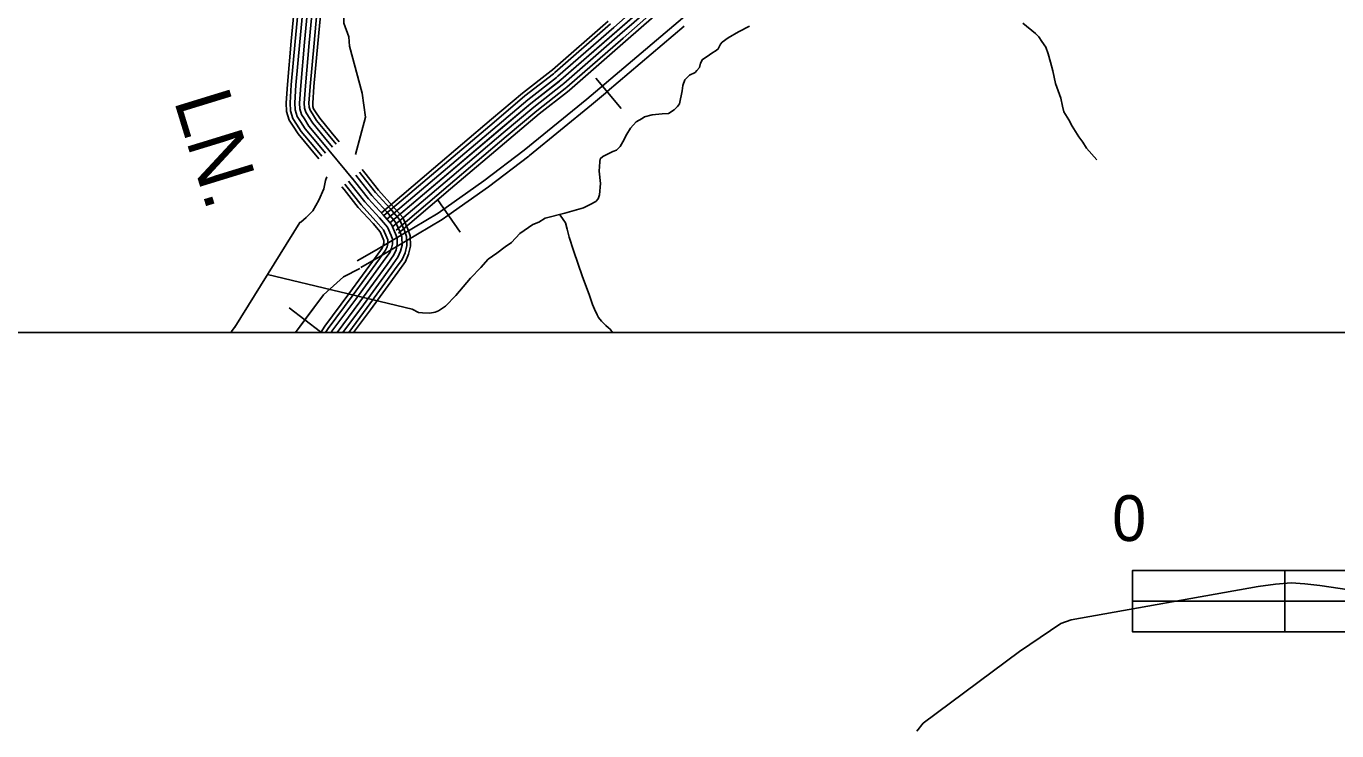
# Model space of a CAD drawing. Extents: x 1577619 to 1828281, y 483481 to 598136.
# Drawn here: x 1672781 to 1681374, y 505510 to 510126 of the extents above; entities that cross this region are included whole.
import ezdxf

# ---------------------------------------------------------------- set-up
doc = ezdxf.new("R2010")
doc.units = 0
for name, color, linetype in [('DESIGN - CONTOURS - Intermediate with optional Text', 7, 'Continuous'), ('DESIGN - ROW - Right-of-Way and Easement Labels', 7, 'Continuous'), ('DESIGN - SHEET - Corner Text', 7, 'Continuous'), ('DESIGN - SHEET - Linework', 7, 'Continuous'), ('DESIGN - TRANSPORTATION - Text', 7, 'Continuous'), ('SURVEY - CONTROL with Text', 7, 'Continuous'), ('SURVEY - TRANSPORTATION - Roads', 7, 'Continuous')]:
    doc.layers.add(name, color=color, linetype=linetype)

msp = doc.modelspace()

# ---------------------------------------------------------------- linework, layer by layer
at = {"layer": 'DESIGN - CONTOURS - Intermediate with optional Text'}
for p, q in [((1676682.7, 509587.5), (1676514.7, 509786)), ((1675627.1, 508777.1), (1675478.1, 508990.2)), ((1674504, 508280), (1674711.5, 508123.4))]:
    msp.add_line(p, q, dxfattribs=at)
for points in [[(1674951, 508587.6), (1675078.1, 508661.1), (1675481.1, 508901.7), (1675782.4, 509112.4), (1676046.1, 509313.4), (1676456.1, 509648.1), (1677512.9, 510542.5), (1678108.9, 511056.8), (1678611.5, 511476.1), (1678813.4, 511646.9), (1678948.4, 511774.5), (1679168.8, 511983.5), (1679370.4, 512186.2), (1679519.7, 512344), (1679684, 512530.1), (1679821.1, 512703.3), (1679957.3, 512912.7), (1680046.6, 513052.1), (1680161.2, 513242.5), (1680189.5, 513292.2)], [(1676590.3, 509699), (1677094, 510125.4)], [(1676080.9, 509278), (1676487.7, 509610.1), (1676591.3, 509697.8)], [(1675545, 508886.7), (1675811.3, 509072.8), (1676076.5, 509275), (1676080.6, 509278.3)], [(1674975.8, 508544.8), (1675103.1, 508618.5), (1675507.9, 508860.2), (1675545.3, 508886.3)], [(1674546, 508119.9), (1674731, 508365.1), (1674862, 508484.2), (1674969.2, 508537.8)], [(1674607.7, 508201.7), (1674731, 508365.1), (1674862, 508484.2), (1674969.2, 508537.8)], [(1674546, 508119.9), (1674607.7, 508201.7)]]:
    msp.add_lwpolyline(points, dxfattribs=at)
at = {"layer": 'DESIGN - SHEET - Corner Text'}
msp.add_lwpolyline([(1680033.1, 506558.8), (1680033.1, 506158.8), (1686033.1, 506158.8), (1686033.1, 506558.8), (1680033.1, 506558.8), (1680033.1, 506358.8), (1686033.1, 506358.8), (1686033.1, 506158.8), (1685033.1, 506158.8), (1685033.1, 506558.8), (1684033.1, 506558.8), (1684033.1, 506158.8), (1683033.1, 506158.8), (1683033.1, 506558.8), (1682033.1, 506558.8), (1682033.1, 506158.8), (1681033.1, 506158.8), (1681033.1, 506558.8)], dxfattribs=at)
for points in [[(1680033.1, 506358.8), (1681033.1, 506358.8), (1681033.1, 506558.8), (1680033.1, 506558.8)], [(1681033.1, 506158.8), (1682033.1, 506158.8), (1682033.1, 506358.8), (1681033.1, 506358.8)]]:
    msp.add_lwpolyline(points, close=True, dxfattribs=at)
at = {"layer": 'DESIGN - SHEET - Linework'}
msp.add_lwpolyline([(1669171.5, 526510.7), (1695618, 526510.7), (1695618, 508119.9), (1669171.5, 508119.9)], close=True, dxfattribs=at)
at = {"layer": 'DESIGN - TRANSPORTATION - Text'}
for points in [[(1674855.8, 510303.7), (1674864.9, 510229.5), (1674863.9, 510145.4), (1674895.5, 510055.2), (1674900.9, 509995), (1674983.1, 509688), (1675005.1, 509529.1), (1674940.6, 509284.3)], [(1679314.2, 510146.2), (1679399.3, 510077.2), (1679421.1, 510056.9), (1679438.8, 510024.7), (1679466.4, 509988.4), (1679481.9, 509944.1), (1679497.3, 509889.9), (1679512.8, 509833.7), (1679529.9, 509751.4), (1679564.9, 509654.9), (1679574.4, 509602.7), (1679584, 509564.6), (1679617.4, 509512.2), (1679639, 509469.9), (1679660.6, 509435.6), (1679682.2, 509401.3), (1679707.8, 509367), (1679733.4, 509326.7), (1679800.5, 509249.9)], [(1674362.7, 508498.9), (1675311.1, 508272.2), (1675352.8, 508249.7), (1675378.7, 508247.4), (1675426.6, 508244.8), (1675462.7, 508252.3), (1675484.8, 508262.1), (1675529, 508291.6), (1675597.8, 508360.8), (1675695, 508475.7), (1675761.7, 508545), (1675810.3, 508600.5), (1675866.7, 508639.8), (1675921.1, 508681.2), (1675963.3, 508708.7), (1676018, 508768.1), (1676102.5, 508827.1), (1676142.7, 508842.7), (1676182.9, 508868.2), (1676313.1, 508900.6), (1676435.3, 508935.2), (1676477.5, 508956.7), (1676515.7, 508978.2), (1676529.9, 508994.1), (1676540.2, 509020), (1676547.1, 509096), (1676538, 509176.2), (1676540.8, 509238.2), (1676545, 509256.2), (1676561.1, 509272), (1676627.4, 509305.2), (1676651.5, 509313), (1676675.7, 509336.7), (1676692.1, 509368.5), (1676718.6, 509418.2), (1676743.1, 509458), (1676779.5, 509499.6), (1676819.7, 509521.1), (1676835.8, 509532.9), (1676885.9, 509544.3), (1676949.9, 509551.6), (1676991.8, 509553), (1677030.1, 509578.6), (1677050.3, 509600.4), (1677064.5, 509616.2), (1677081.5, 509702.1), (1677085.9, 509738.1), (1677098.3, 509774), (1677130.6, 509805.6), (1677166.8, 509823.2), (1677178.9, 509835.1), (1677195.1, 509854.9), (1677201.4, 509882.9), (1677215.7, 509908.7), (1677245.9, 509926.4), (1677276.1, 509950), (1677304.3, 509965.7), (1677318.4, 509977.5), (1677332.7, 510007.4), (1677344.9, 510021.2), (1677383.1, 510048.8), (1677451.5, 510090), (1677523.8, 510127.2)], [(1674752.7, 509138.5), (1674744, 509114.9), (1674731.4, 509061), (1674700.5, 508985.3), (1674659.7, 508915.7), (1674617.3, 508872.2), (1674581, 508842.6), (1674575.6, 508840.7), (1674148.3, 508154.7)], [(1676279.2, 508892.8), (1676282.7, 508887.9), (1676302.4, 508859.7), (1676316.2, 508837.5), (1676327.7, 508795.3), (1676341.2, 508743.1), (1676370.3, 508656.7), (1676428.5, 508483.9), (1676471.3, 508367.3), (1676494.6, 508303), (1676506.3, 508272.8), (1676523.9, 508234.6), (1676533.7, 508218.4), (1676553.4, 508194.2), (1676581.1, 508165.9), (1676598.9, 508149.7), (1676608.8, 508141.5), (1676626, 508119.9)], [(1674125, 508119.9), (1674126.5, 508125.4), (1674151.6, 508159.2)]]:
    msp.add_lwpolyline(points, dxfattribs=at)
at = {"layer": 'SURVEY - CONTROL with Text'}
msp.add_lwpolyline([(1685212, 508230.8), (1684466.5, 507717.3), (1683864.4, 507261.8), (1682823.3, 506530.2), (1682667.7, 506466.7), (1682547.1, 506427.7), (1682420.6, 506392.7), (1682297.8, 506365.7), (1682085.5, 506341.2), (1681750, 506389), (1681262.7, 506460.5), (1681163.7, 506472.5), (1681074.2, 506478.3), (1680971.1, 506470.5), (1680858.9, 506455.6), (1679631, 506236.7), (1679564.8, 506213.4), (1679293, 506030.1), (1678660.7, 505558.7), (1678619.6, 505507.6)], dxfattribs=at)
at = {"layer": 'SURVEY - TRANSPORTATION - Roads'}
for points in [[(1677009.3, 510446.6), (1676820.1, 510280.6), (1676633.1, 510117.4)], [(1677029.7, 510423.4), (1676840.5, 510257.2), (1676653.5, 510094)], [(1677050.2, 510400.1), (1676860.9, 510233.9), (1676673.9, 510070.6)], [(1674551.2, 510375.9), (1674518.8, 510028.8), (1674493.1, 509743.6), (1674485.2, 509623.1), (1674488.3, 509567.9), (1674505.8, 509511), (1674531.7, 509470.9), (1674563.8, 509420.1), (1674646.1, 509320.5), (1674699, 509256.8)], [(1674576.9, 510373.8), (1674544.4, 510026.5), (1674518.7, 509741.6), (1674510.9, 509622.9), (1674513.8, 509572.5), (1674529.3, 509522), (1674553.4, 509484.7), (1674584.7, 509435.2), (1674665.9, 509336.9), (1674718.7, 509273.3)], [(1674607.8, 510371.3), (1674575.3, 510023.6), (1674549.6, 509739.2), (1674542, 509622.8), (1674544.6, 509578), (1674557.7, 509535.2), (1674579.5, 509501.4), (1674609.8, 509453.4), (1674689.8, 509356.7), (1674742.5, 509293.2)], [(1674638.7, 510368.8), (1674606.2, 510020.8), (1674580.5, 509736.7), (1674573, 509622.7), (1674575.3, 509583.5), (1674586.1, 509548.4), (1674605.6, 509518.1), (1674635, 509471.7), (1674713.6, 509376.5), (1674933.9, 509111.2), (1675024.3, 508995.8), (1675120.8, 508890.4), (1675175.9, 508825.6), (1675203.1, 508765.1), (1675212.7, 508737), (1675214.1, 508694.9), (1675205.7, 508660.9), (1675191.3, 508627.1), (1675146.5, 508565.6), (1674967.5, 508319.7), (1674818.8, 508119.9)], [(1674638.7, 510368.8), (1674606.2, 510020.8), (1674580.5, 509736.7), (1674573, 509622.7), (1674575.3, 509583.5), (1674586.1, 509548.4), (1674605.6, 509518.1), (1674635, 509471.7), (1674713.6, 509376.5), (1674766.2, 509313.2)], [(1674669.6, 510366.3), (1674637, 510017.9), (1674611.4, 509734.3), (1674604.1, 509622.6), (1674606, 509589), (1674614.4, 509561.6), (1674631.8, 509534.8), (1674660.1, 509489.9), (1674737.5, 509396.3), (1674790, 509333.1)], [(1674700.5, 510363.8), (1674667.9, 510015.1), (1674642.3, 509731.9), (1674635.1, 509622.4), (1674636.7, 509594.5), (1674642.8, 509574.8), (1674657.9, 509551.5), (1674685.3, 509508.1), (1674761.4, 509416), (1674813.7, 509353)], [(1674725.1, 510361.8), (1674692.5, 510012.8), (1674667, 509730), (1674659.9, 509622.3), (1674661.3, 509598.9), (1674665.4, 509585.4), (1674678.7, 509564.8), (1674705.3, 509522.6), (1674780.4, 509431.8), (1674832.7, 509368.9)], [(1677070.6, 510376.8), (1676881.3, 510210.6), (1676694.3, 510047.3)], [(1677087.6, 510357.4), (1676898.3, 510191.2), (1676711.2, 510027.9)], [(1676840.5, 510257.2), (1676286.9, 509774), (1676089.1, 509620.4), (1675165.5, 508837.8)], [(1676596.5, 510159.3), (1676231.7, 509841), (1676223.2, 509834.3)], [(1676612.7, 510140.7), (1676247.5, 509821.9), (1676238.3, 509814.8)], [(1676633.1, 510117.4), (1676267.2, 509797.9), (1676257.3, 509790.3)], [(1676653.5, 510094), (1676286.9, 509774), (1676276.3, 509765.8)], [(1676673.9, 510070.7), (1676306.6, 509750), (1676295.4, 509741.3)], [(1676694.3, 510047.3), (1676326.3, 509726.1), (1676314.4, 509716.8)], [(1676711.2, 510027.9), (1676342.7, 509706.2), (1676330.1, 509696.5)], [(1676223.2, 509834.3), (1676034.5, 509687.8), (1675832.5, 509516.6)], [(1676238.3, 509814.8), (1676050.1, 509668.6), (1675848.4, 509497.7)], [(1676257.4, 509790.3), (1676069.6, 509644.5), (1675868.5, 509474.1)], [(1676276.4, 509765.8), (1676089.1, 509620.4), (1675888.5, 509450.4)], [(1676295.4, 509741.3), (1676108.7, 509596.3), (1675908.6, 509426.8)], [(1676314.4, 509716.8), (1676128.2, 509572.3), (1675928.6, 509403.1)], [(1676330.2, 509696.5), (1676144.4, 509552.3), (1675945.2, 509383.5)], [(1675832.5, 509516.6), (1675451, 509193.4)], [(1675848.4, 509497.7), (1675467, 509174.5)], [(1675868.5, 509474.1), (1675487, 509150.8)], [(1675888.5, 509450.4), (1675507.1, 509127.2)], [(1675908.6, 509426.8), (1675527.1, 509103.5)], [(1675928.6, 509403.1), (1675547.2, 509079.9)], [(1675945.2, 509383.5), (1675563.8, 509060.3)], [(1675451, 509193.4), (1675109.5, 508903.9)], [(1674894.2, 509110.4), (1674909.8, 509091.7), (1675000.6, 508975.8), (1675097.6, 508869.9), (1675149.4, 508808.8), (1675174.2, 508753.7), (1675181.9, 508731.3), (1675183, 508698.1), (1675176.2, 508670.8), (1675164.1, 508642.5), (1675121.5, 508583.8), (1674942.6, 508338.1), (1674785.6, 508127.2), (1674780.8, 508119.9)], [(1674918, 509130.4), (1674933.9, 509111.2), (1675024.3, 508995.8), (1675120.8, 508890.4), (1675175.9, 508825.6), (1675203.1, 508765.1), (1675212.7, 508737), (1675214.1, 508694.9), (1675205.7, 508660.9), (1675191.3, 508627.1), (1675146.5, 508565.6), (1674967.5, 508319.7), (1674818.8, 508119.9)], [(1674941.8, 509150.3), (1674958, 509130.6), (1675048, 509015.9), (1675144.1, 508910.9), (1675202.4, 508842.3), (1675231.9, 508776.5), (1675243.5, 508742.6), (1675245.3, 508691.6), (1675235.2, 508651.1), (1675218.4, 508611.7), (1675171.6, 508547.4), (1674992.5, 508301.3), (1674857.4, 508119.9)], [(1674965.5, 509170.2), (1674982.2, 509150.1), (1675071.6, 509035.9), (1675167.3, 508931.4), (1675228.8, 508859), (1675260.8, 508787.9), (1675274.3, 508748.3), (1675276.4, 508688.3), (1675264.7, 508641.2), (1675245.6, 508596.3), (1675196.7, 508529.1), (1675017.5, 508282.9), (1674896.1, 508119.9)], [(1674984.4, 509186.1), (1675001.4, 509165.6), (1675090.5, 509051.9), (1675185.8, 508947.8), (1675249.9, 508872.3), (1675283.8, 508797), (1675298.9, 508752.8), (1675301.2, 508685.7), (1675288.2, 508633.3), (1675267.2, 508584), (1675216.6, 508514.6), (1675037.4, 508268.3), (1674926.9, 508119.9)], [(1675467, 509174.5), (1675125.4, 508885.1)], [(1675487, 509150.9), (1675145.5, 508861.4)], [(1675507.1, 509127.2), (1675165.5, 508837.8)], [(1674850.8, 509073.9), (1674865.6, 509056.1), (1674957.3, 508939.1), (1675055, 508832.4), (1675101, 508778.2), (1675121.4, 508732.9), (1675125.5, 508720.9), (1675126.1, 508704.1), (1675122.3, 508688.9), (1675114.5, 508670.6), (1675075.6, 508617.2), (1674896.9, 508371.7), (1674739, 508159.7), (1674713.1, 508119.9)], [(1674870.5, 509090.5), (1674885.7, 509072.2), (1674977, 508955.7), (1675074.3, 508849.4), (1675122.9, 508792.1), (1675145.3, 508742.3), (1675151, 508725.6), (1675151.9, 508701.4), (1675146.7, 508680.7), (1675137, 508657.9), (1675096.4, 508602.1), (1674917.6, 508356.4), (1674760.1, 508144.9), (1674743.8, 508119.9)], [(1675527.1, 509103.6), (1675185.6, 508814.1)], [(1675547.2, 509079.9), (1675205.6, 508790.5)], [(1675563.8, 509060.3), (1675222.2, 508770.8)]]:
    msp.add_lwpolyline(points, dxfattribs=at)

# ---------------------------------------------------------------- texts
at = {"layer": 'DESIGN - ROW - Right-of-Way and Easement Labels'}
msp.add_text('LN.', height=370.01, rotation=287.06295, dxfattribs=at).set_placement((1673747.5, 509640.3))
at = {"layer": 'DESIGN - SHEET - Corner Text'}
msp.add_text('0', height=300, dxfattribs=at).set_placement((1679901.1, 506752.8))

doc.saveas('drawing.dxf')
